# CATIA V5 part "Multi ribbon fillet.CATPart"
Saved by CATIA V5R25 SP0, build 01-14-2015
Part number: Part1
Bounding box of the stored display mesh (mm): x -200 to 0, y -56.059 to 216.476, z -47.66 to 28.91
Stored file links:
  E:\cadcim\Projects\CATIA V5-6R2015_Menuscript\GSD_cat_v5-6r2015\Part_files\Multi ribbon fillet.CATPart
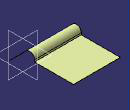
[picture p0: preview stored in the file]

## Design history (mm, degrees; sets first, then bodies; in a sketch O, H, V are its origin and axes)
Set1
  Sketch1 on yz-plane, origin (0, 0, 0), H (0, 1, 0), V (0, 0, 1)
    point P1 (0, 30)
    line L1 (0, 30) -> (50, 30)
    line L2 (50, 30) -> (50, 0)
    point P3 (50, 0)
    line L3 (50, 0) -> (216.476, 0)
    length L1 = 50
    length L2 = 30
    coincidence: P1 V, P3 H
    horizontal: L1 H, L3 H
    vertical: L2 V
  Extrude1: Lim1 200, Lim2 0, Element1 Sketch1
  Sketch2 on yz-plane, origin (0, 0, 0), H (0, 1, 0), V (0, 0, 1)
    line L1 (35.5115, 44.1839) -> (-56.0594, -47.6596)
  Extrude2: Lim1 200, Lim2 0, Element1 Sketch2
  Fillet1: type BiTangent, Element1 Extrude2, Element2 Extrude1, Radius 21, FacesToKeep face of Extrude1 from Sketch1.L2
Body1 (main body)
